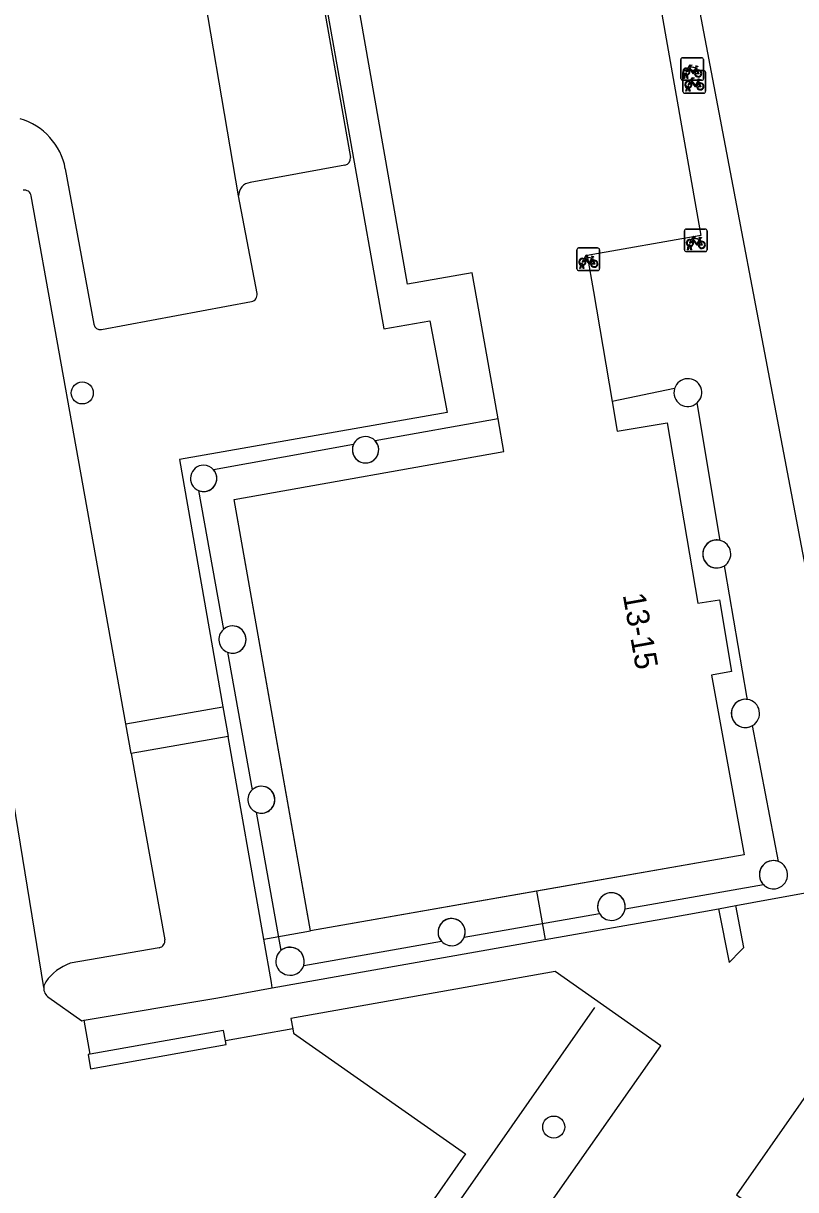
# Model space of a CAD drawing. Extents: x 152881 to 155736, y 382924 to 386919.
# Drawn here: x 155208.5 to 155242.8, y 385255.6 to 385307.3 of the extents above; entities that cross this region are included whole.
import ezdxf

# ---------------------------------------------------------------- set-up
doc = ezdxf.new("R2010")
doc.units = 0
for name, color, linetype in [('IMGEO_Boom', 7, 'Continuous'), ('IMGEO_Fietsenrek', 7, 'Continuous'), ('IMGEO_Hek', 7, 'Continuous'), ('IMGEO_Pand', 7, 'Continuous'), ('IMGEO_Pand_nummerreeks', 7, 'Continuous'), ('IMGEO_Pand_overbouw', 7, 'Continuous'), ('IMGEO_Parkeervlak_open', 7, 'Continuous'), ('IMGEO_Rijbaan_lokaal_open', 7, 'Continuous'), ('IMGEO_Voetpad_halfverhard', 7, 'Continuous'), ('IMGEO_Voetpad_open', 7, 'Continuous')]:
    doc.layers.add(name, color=color, linetype=linetype)

msp = doc.modelspace()

# ---------------------------------------------------------------- linework, layer by layer
at = {"layer": 'IMGEO_Boom'}
for centre in [(155211.143, 385290.912), (155232.043, 385258.375)]:
    msp.add_circle(centre, 0.489, dxfattribs=at)
at = {"layer": 'IMGEO_Fietsenrek'}
for p, q in [((155237.676, 385304.847), (155237.676, 385305.688)), ((155237.676, 385305.688), (155237.676, 385304.847)), ((155237.751, 385305.772), (155238.592, 385305.772)), ((155238.592, 385305.772), (155237.751, 385305.772)), ((155238.676, 385305.697), (155238.676, 385304.856)), ((155238.676, 385304.856), (155238.676, 385305.697)), ((155237.769, 385304.274), (155237.769, 385305.115)), ((155237.769, 385305.115), (155237.769, 385304.274)), ((155237.803, 385304.856), (155237.842, 385305.016)), ((155237.844, 385305.199), (155238.685, 385305.199)), ((155238.685, 385305.199), (155237.844, 385305.199)), ((155237.914, 385305.028), (155237.913, 385305.032)), ((155237.945, 385305.039), (155237.946, 385305.032)), ((155238.363, 385305.321), (155238.399, 385305.226)), ((155238.769, 385305.124), (155238.769, 385304.283)), ((155238.769, 385304.283), (155238.769, 385305.124)), ((155238.601, 385304.772), (155237.76, 385304.772)), ((155237.76, 385304.772), (155238.601, 385304.772)), ((155237.837, 385304.856), (155237.803, 385304.856)), ((155237.872, 385305.004), (155237.837, 385304.856)), ((155237.955, 385304.856), (155237.921, 385304.998)), ((155237.953, 385305.002), (155237.988, 385304.856)), ((155237.988, 385304.856), (155237.955, 385304.856)), ((155238.456, 385304.748), (155238.492, 385304.653)), ((155238.694, 385304.199), (155237.853, 385304.199)), ((155237.853, 385304.199), (155238.694, 385304.199)), ((155237.896, 385304.283), (155237.935, 385304.443)), ((155237.93, 385304.283), (155237.896, 385304.283)), ((155237.965, 385304.431), (155237.93, 385304.283)), ((155238.007, 385304.455), (155238.006, 385304.459)), ((155238.048, 385304.283), (155238.014, 385304.425)), ((155238.038, 385304.466), (155238.039, 385304.459)), ((155238.046, 385304.429), (155238.081, 385304.283)), ((155238.081, 385304.283), (155238.048, 385304.283)), ((155237.835, 385297.251), (155237.835, 385298.092)), ((155237.835, 385298.092), (155237.835, 385297.251)), ((155237.91, 385298.176), (155238.751, 385298.176)), ((155238.751, 385298.176), (155237.91, 385298.176)), ((155238.835, 385298.101), (155238.835, 385297.26)), ((155238.835, 385297.26), (155238.835, 385298.101)), ((155233.069, 385296.413), (155233.069, 385297.254)), ((155233.069, 385297.254), (155233.069, 385296.413)), ((155233.144, 385297.338), (155233.985, 385297.338)), ((155233.985, 385297.338), (155233.144, 385297.338)), ((155234.069, 385297.263), (155234.069, 385296.422)), ((155234.069, 385296.422), (155234.069, 385297.263)), ((155237.962, 385297.26), (155238.001, 385297.42)), ((155237.996, 385297.26), (155237.962, 385297.26)), ((155238.031, 385297.408), (155237.996, 385297.26)), ((155238.073, 385297.432), (155238.072, 385297.436)), ((155238.114, 385297.26), (155238.08, 385297.402)), ((155238.104, 385297.443), (155238.105, 385297.436)), ((155238.112, 385297.406), (155238.147, 385297.26)), ((155238.147, 385297.26), (155238.114, 385297.26)), ((155238.522, 385297.725), (155238.558, 385297.63)), ((155233.756, 385296.887), (155233.792, 385296.792)), ((155238.76, 385297.176), (155237.919, 385297.176)), ((155237.919, 385297.176), (155238.76, 385297.176)), ((155233.994, 385296.338), (155233.153, 385296.338)), ((155233.153, 385296.338), (155233.994, 385296.338)), ((155233.196, 385296.422), (155233.235, 385296.582)), ((155233.23, 385296.422), (155233.196, 385296.422)), ((155233.265, 385296.57), (155233.23, 385296.422)), ((155233.307, 385296.594), (155233.306, 385296.598)), ((155233.348, 385296.422), (155233.314, 385296.564)), ((155233.338, 385296.605), (155233.339, 385296.598)), ((155233.346, 385296.568), (155233.381, 385296.422)), ((155233.381, 385296.422), (155233.348, 385296.422))]:
    msp.add_line(p, q, dxfattribs=at)
for points in [[(155238.01, 385305.246), (155237.958, 385305.156), (155237.918, 385305.131), (155237.919, 385305.178), (155237.974, 385305.272)], [(155237.989, 385305.298), (155238.084, 385305.462), (155238.17, 385305.448), (155238.172, 385305.439), (155238.116, 385305.428), (155238.089, 385305.383), (155238.345, 385305.342)], [(155238.285, 385305.054), (155238.235, 385305.054), (155238.044, 385305.305), (155238.025, 385305.273)], [(155238.332, 385305.317), (155238.075, 385305.358), (155238.058, 385305.329), (155238.225, 385305.109), (155238.332, 385305.317)], [(155238.38, 385305.219), (155238.35, 385305.296), (155238.241, 385305.078), (155238.284, 385305.078)], [(155238.314, 385305.078), (155238.434, 385305.077), (155238.39, 385305.191)], [(155238.41, 385305.198), (155238.465, 385305.053), (155238.315, 385305.053)], [(155238.345, 385305.342), (155238.37, 385305.391), (155238.364, 385305.395), (155238.341, 385305.399), (155238.329, 385305.406), (155238.328, 385305.409), (155238.33, 385305.414), (155238.425, 385305.399), (155238.427, 385305.389), (155238.417, 385305.376), (155238.405, 385305.37), (155238.391, 385305.376), (155238.363, 385305.321)], [(155238.103, 385304.673), (155238.051, 385304.583), (155238.011, 385304.558), (155238.012, 385304.605), (155238.067, 385304.699)], [(155238.082, 385304.725), (155238.177, 385304.889), (155238.263, 385304.875), (155238.265, 385304.866), (155238.209, 385304.855), (155238.182, 385304.81), (155238.438, 385304.769)], [(155238.378, 385304.481), (155238.328, 385304.481), (155238.137, 385304.732), (155238.118, 385304.7)], [(155238.425, 385304.744), (155238.168, 385304.785), (155238.151, 385304.756), (155238.318, 385304.536), (155238.425, 385304.744)], [(155238.473, 385304.646), (155238.443, 385304.723), (155238.334, 385304.505), (155238.377, 385304.505)], [(155238.407, 385304.505), (155238.527, 385304.504), (155238.483, 385304.618)], [(155238.503, 385304.625), (155238.558, 385304.48), (155238.408, 385304.48)], [(155238.438, 385304.769), (155238.463, 385304.818), (155238.457, 385304.822), (155238.434, 385304.826), (155238.422, 385304.833), (155238.421, 385304.836), (155238.423, 385304.841), (155238.518, 385304.826), (155238.52, 385304.816), (155238.51, 385304.803), (155238.498, 385304.797), (155238.484, 385304.803), (155238.456, 385304.748)], [(155238.148, 385297.702), (155238.243, 385297.866), (155238.329, 385297.852), (155238.331, 385297.843), (155238.275, 385297.832), (155238.248, 385297.787), (155238.504, 385297.746)], [(155238.504, 385297.746), (155238.529, 385297.795), (155238.523, 385297.799), (155238.5, 385297.803), (155238.488, 385297.81), (155238.487, 385297.813), (155238.489, 385297.818), (155238.584, 385297.803), (155238.586, 385297.793), (155238.576, 385297.78), (155238.564, 385297.774), (155238.55, 385297.78), (155238.522, 385297.725)], [(155238.169, 385297.65), (155238.117, 385297.56), (155238.077, 385297.535), (155238.078, 385297.582), (155238.133, 385297.676)], [(155238.444, 385297.458), (155238.394, 385297.458), (155238.203, 385297.709), (155238.184, 385297.677)], [(155238.491, 385297.721), (155238.234, 385297.762), (155238.217, 385297.733), (155238.384, 385297.513), (155238.491, 385297.721)], [(155238.539, 385297.623), (155238.509, 385297.7), (155238.4, 385297.482), (155238.443, 385297.482)], [(155238.473, 385297.482), (155238.593, 385297.481), (155238.549, 385297.595)], [(155238.569, 385297.602), (155238.624, 385297.457), (155238.474, 385297.457)], [(155233.403, 385296.812), (155233.351, 385296.722), (155233.311, 385296.697), (155233.312, 385296.744), (155233.367, 385296.838)], [(155233.382, 385296.864), (155233.477, 385297.028), (155233.563, 385297.014), (155233.565, 385297.005), (155233.509, 385296.994), (155233.482, 385296.949), (155233.738, 385296.908)], [(155233.678, 385296.62), (155233.628, 385296.62), (155233.437, 385296.871), (155233.418, 385296.839)], [(155233.725, 385296.883), (155233.468, 385296.924), (155233.451, 385296.895), (155233.618, 385296.675), (155233.725, 385296.883)], [(155233.773, 385296.785), (155233.743, 385296.862), (155233.634, 385296.644), (155233.677, 385296.644)], [(155233.707, 385296.644), (155233.827, 385296.643), (155233.783, 385296.757)], [(155233.803, 385296.764), (155233.858, 385296.619), (155233.708, 385296.619)], [(155233.738, 385296.908), (155233.763, 385296.957), (155233.757, 385296.961), (155233.734, 385296.965), (155233.722, 385296.972), (155233.721, 385296.975), (155233.723, 385296.98), (155233.818, 385296.965), (155233.82, 385296.955), (155233.81, 385296.942), (155233.798, 385296.936), (155233.784, 385296.942), (155233.756, 385296.887)]]:
    msp.add_lwpolyline(points, dxfattribs=at)
for centre, radius, start, end in [((155237.754, 385305.694), 0.0779, 92.4484, 184.2845), ((155237.754, 385305.694), 0.0779, 92.4484, 184.2845), ((155238.598, 385305.694), 0.0779, 2.4484, 94.2845), ((155238.598, 385305.694), 0.0779, 2.4484, 94.2845), ((155237.916, 385305.157), 0.159, 62.6766, 242.1369), ((155237.847, 385305.121), 0.0779, 92.4484, 184.2845), ((155237.847, 385305.121), 0.0779, 92.4484, 184.2845), ((155237.916, 385305.157), 0.129, 63.3192, 238.903), ((155237.896, 385305.028), 0.0499, 12.8025, 158.6934), ((155237.896, 385305.028), 0.0174, 12.8025, 163.4502), ((155237.916, 385305.157), 0.129, 253.415, 269.0204), ((155237.916, 385305.157), 0.129, 283.6043, 43.4302), ((155237.916, 385305.157), 0.159, 283.5766, 46.6042), ((155238.443, 385305.073), 0.159, 113.3408, 178.3217), ((155238.443, 385305.073), 0.159, 187.0065, 105.7708), ((155238.443, 385305.073), 0.129, 113.923, 177.9556), ((155238.443, 385305.073), 0.129, 188.6715, 104.5883), ((155238.691, 385305.121), 0.0779, 2.4484, 94.2845), ((155238.691, 385305.121), 0.0779, 2.4484, 94.2845), ((155237.754, 385304.85), 0.0779, 182.4484, 274.2845), ((155237.754, 385304.85), 0.0779, 182.4484, 274.2845), ((155238.009, 385304.584), 0.159, 62.6766, 242.1369), ((155237.916, 385305.157), 0.159, 253.9967, 271.7867), ((155238.009, 385304.584), 0.129, 63.3192, 238.903), ((155237.989, 385304.455), 0.0499, 12.8025, 158.6934), ((155238.009, 385304.584), 0.129, 283.6043, 43.4302), ((155238.009, 385304.584), 0.159, 283.5766, 46.6042), ((155238.536, 385304.5), 0.159, 113.3408, 178.3217), ((155238.536, 385304.5), 0.159, 187.0065, 105.7708), ((155238.536, 385304.5), 0.129, 113.923, 177.9556), ((155238.536, 385304.5), 0.129, 188.6715, 104.5883), ((155238.598, 385304.85), 0.0779, 272.4484, 4.2845), ((155238.598, 385304.85), 0.0779, 272.4484, 4.2845), ((155237.847, 385304.277), 0.0779, 182.4484, 274.2845), ((155237.847, 385304.277), 0.0779, 182.4484, 274.2845), ((155238.009, 385304.584), 0.159, 253.9967, 271.7867), ((155237.989, 385304.455), 0.0174, 12.8025, 163.4502), ((155238.009, 385304.584), 0.129, 253.415, 269.0204), ((155238.691, 385304.277), 0.0779, 272.4484, 4.2845), ((155238.691, 385304.277), 0.0779, 272.4484, 4.2845), ((155237.913, 385298.098), 0.0779, 92.4484, 184.2845), ((155237.913, 385298.098), 0.0779, 92.4484, 184.2845), ((155238.757, 385298.098), 0.0779, 2.4484, 94.2845), ((155238.757, 385298.098), 0.0779, 2.4484, 94.2845), ((155233.147, 385297.26), 0.0779, 92.4484, 184.2845), ((155233.147, 385297.26), 0.0779, 92.4484, 184.2845), ((155233.991, 385297.26), 0.0779, 2.4484, 94.2845), ((155233.991, 385297.26), 0.0779, 2.4484, 94.2845), ((155238.075, 385297.561), 0.159, 62.6766, 242.1369), ((155238.075, 385297.561), 0.129, 63.3192, 238.903), ((155238.055, 385297.432), 0.0499, 12.8025, 158.6934), ((155238.075, 385297.561), 0.159, 253.9967, 271.7867), ((155238.055, 385297.432), 0.0174, 12.8025, 163.4502), ((155238.075, 385297.561), 0.129, 253.415, 269.0204), ((155238.075, 385297.561), 0.129, 283.6043, 43.4302), ((155238.075, 385297.561), 0.159, 283.5766, 46.6042), ((155238.602, 385297.477), 0.159, 113.3408, 178.3217), ((155238.602, 385297.477), 0.159, 187.0065, 105.7708), ((155238.602, 385297.477), 0.129, 113.923, 177.9556), ((155238.602, 385297.477), 0.129, 188.6715, 104.5883), ((155238.757, 385297.254), 0.0779, 272.4484, 4.2845), ((155238.757, 385297.254), 0.0779, 272.4484, 4.2845), ((155233.309, 385296.723), 0.159, 62.6766, 242.1369), ((155233.309, 385296.723), 0.129, 63.3192, 238.903), ((155233.309, 385296.723), 0.129, 283.6043, 43.4302), ((155233.309, 385296.723), 0.159, 283.5766, 46.6042), ((155233.836, 385296.639), 0.159, 113.3408, 178.3217), ((155233.836, 385296.639), 0.159, 187.0065, 105.7708), ((155233.836, 385296.639), 0.129, 113.923, 177.9556), ((155233.836, 385296.639), 0.129, 188.6715, 104.5883), ((155237.913, 385297.254), 0.0779, 182.4484, 274.2845), ((155237.913, 385297.254), 0.0779, 182.4484, 274.2845), ((155233.147, 385296.416), 0.0779, 182.4484, 274.2845), ((155233.147, 385296.416), 0.0779, 182.4484, 274.2845), ((155233.289, 385296.594), 0.0499, 12.8025, 158.6934), ((155233.309, 385296.723), 0.159, 253.9967, 271.7867), ((155233.289, 385296.594), 0.0174, 12.8025, 163.4502), ((155233.309, 385296.723), 0.129, 253.415, 269.0204), ((155233.991, 385296.416), 0.0779, 272.4484, 4.2845), ((155233.991, 385296.416), 0.0779, 272.4484, 4.2845)]:
    msp.add_arc(centre, radius, start, end, dxfattribs=at)
at = {"layer": 'IMGEO_Hek'}
msp.add_lwpolyline([(155222.768, 385247.792), (155233.861, 385263.666)], dxfattribs=at)
at = {"layer": 'IMGEO_Pand'}
for points in [[(155221.26, 385267.071), (155220.388, 385271.995), (155217.872, 385286.193), (155229.836, 385288.313), (155229.578, 385289.769), (155228.738, 385294.514), (155228.432, 385296.24), (155225.556, 385295.735), (155218.64, 385335.1)], [(155236.615, 385308.968), (155238.561, 385297.888), (155233.524, 385297.002), (155233.796, 385295.402), (155234.623, 385290.536), (155234.847, 385289.218), (155237.065, 385289.595), (155238.427, 385281.592), (155239.38, 385281.749), (155239.913, 385278.573), (155239.026, 385278.41), (155240.487, 385270.437), (155231.28, 385268.825)], [(155231.28, 385268.825), (155221.26, 385267.071)]]:
    msp.add_lwpolyline(points, dxfattribs=at)
for centre, radius, start, end in [((155237.981, 385290.925), 0.614, 162.4131, 312.5112), ((155237.985, 385290.93), 0.616, 311.9155, 163.0087), ((155223.7, 385288.394), 0.584, 157.1979, 269.921), ((155223.698, 385288.396), 0.582, 89.8707, 157.2634), ((155223.7, 385288.397), 0.581, 42.9862, 90.0658), ((155223.699, 385288.394), 0.584, 269.9744, 43.1649), ((155216.525, 385287.127), 0.584, 90.0587, 246.9681), ((155216.526, 385287.132), 0.579, 40.906, 90.2061), ((155216.525, 385287.127), 0.584, 269.9307, 41.1814), ((155216.529, 385287.154), 0.611, 247.6128, 269.5741), ((155239.267, 385283.775), 0.621, 92.3835, 276.0178), ((155239.265, 385283.797), 0.6, 75.3484, 92.3286), ((155239.267, 385283.775), 0.62, 302.8989, 76.0092), ((155239.26, 385283.789), 0.636, 276.4987, 302.7555), ((155217.802, 385279.982), 0.603, 132.0143, 248.1445), ((155217.801, 385279.985), 0.6, 89.9386, 132.1364), ((155217.802, 385279.982), 0.603, 269.9525, 90.0475), ((155217.804, 385279.994), 0.614, 248.4247, 269.8422), ((155240.538, 385276.707), 0.627, 102.8722, 254.4875), ((155240.535, 385276.715), 0.618, 81.1536, 102.7963), ((155240.537, 385276.707), 0.626, 300.0861, 81.4871), ((155240.536, 385276.706), 0.626, 254.6502, 300.2737), ((155219.079, 385272.887), 0.592, 89.8135, 133.5482), ((155219.082, 385272.883), 0.597, 269.952, 90.048), ((155219.082, 385272.883), 0.597, 133.4863, 246.7226), ((155219.08, 385272.879), 0.593, 246.784, 270.1276), ((155241.779, 385269.559), 0.625, 97.1764, 224.3353), ((155241.781, 385269.562), 0.622, 69.2973, 97.3938), ((155241.779, 385269.559), 0.625, 277.9472, 69.1635), ((155241.777, 385269.555), 0.621, 224.183, 278.1106), ((155234.595, 385268.149), 0.613, 80.4911, 209.8045), ((155234.596, 385268.148), 0.613, 350.1144, 80.6244), ((155234.596, 385268.15), 0.615, 209.8212, 270.9844), ((155234.595, 385268.149), 0.614, 271.1235, 350.0473), ((155227.516, 385267.015), 0.602, 87.9786, 221.9001), ((155227.515, 385267.014), 0.602, 338.2752, 87.9433), ((155227.516, 385267.015), 0.602, 221.8665, 338.1819), ((155220.344, 385265.728), 0.615, 73.2631, 130.4641), ((155220.369, 385265.719), 0.617, 343.0855, 75.7837), ((155220.346, 385265.724), 0.62, 130.3764, 258.8912), ((155220.367, 385265.72), 0.62, 256.9396, 343.0372)]:
    msp.add_arc(centre, radius, start, end, dxfattribs=at)
at = {"layer": 'IMGEO_Pand_overbouw'}
for points in [[(155237.396, 385291.11), (155234.623, 385290.536), (155234.847, 385289.218), (155237.065, 385289.595), (155238.427, 385281.592), (155239.38, 385281.749), (155239.913, 385278.573), (155239.026, 385278.41), (155240.487, 385270.437), (155221.26, 385267.071), (155217.872, 385286.193), (155229.836, 385288.313), (155229.578, 385289.769), (155224.125, 385288.793)], [(155239.417, 385284.377), (155238.396, 385290.472)], [(155223.161, 385288.621), (155216.964, 385287.511)], [(155216.296, 385286.589), (155217.399, 385280.43)], [(155239.633, 385283.084), (155239.604, 385283.254)], [(155240.63, 385277.326), (155240.601, 385277.479), (155239.633, 385283.084)], [(155217.578, 385279.423), (155218.671, 385273.316)], [(155242.001, 385270.144), (155240.851, 385276.166)], [(155218.846, 385272.334), (155219.945, 385266.196)], [(155235.2, 385268.043), (155241.332, 385269.122)], [(155228.075, 385266.791), (155234.063, 385267.844)], [(155220.96, 385265.539), (155227.068, 385266.613)]]:
    msp.add_lwpolyline(points, dxfattribs=at)
for centre, radius, start, end in [((155237.981, 385290.925), 0.614, 162.4131, 312.5112), ((155223.699, 385288.394), 0.584, 157.1062, 43.1267), ((155216.524, 385287.127), 0.584, 246.9952, 41.1572), ((155239.266, 385283.775), 0.621, 75.9382, 302.9699), ((155217.802, 385279.982), 0.603, 248.1403, 132.0184), ((155240.537, 385276.707), 0.626, 81.4241, 300.1491), ((155219.081, 385272.883), 0.597, 246.7908, 133.4182), ((155241.78, 385269.559), 0.626, 69.2738, 224.3088), ((155234.596, 385268.148), 0.613, 350.149, 209.7059), ((155227.516, 385267.015), 0.602, 338.1941, 221.8543), ((155220.348, 385265.707), 0.634, 344.6564, 129.5144)]:
    msp.add_arc(centre, radius, start, end, dxfattribs=at)
at = {"layer": 'IMGEO_Parkeervlak_open'}
for points in [[(155217.142, 385337.508), (155217.044, 385337.456), (155216.999, 385337.43), (155216.957, 385337.399), (155216.918, 385337.366), (155216.882, 385337.329), (155216.849, 385337.288), (155216.821, 385337.245), (155216.796, 385337.2), (155216.775, 385337.152), (155216.759, 385337.103), (155216.747, 385337.053), (155216.74, 385337.002), (155216.738, 385336.95), (155216.74, 385336.898), (155216.747, 385336.847), (155217.107, 385334.819), (155217.164, 385334.497), (155223.027, 385301.353)], [(155222.785, 385301.006), (155218.592, 385300.24)], [(155213.084, 385276.243), (155208.887, 385299.655)], [(155213.32, 385274.929), (155214.8, 385266.672)], [(155214.556, 385266.324), (155210.614, 385265.632)]]:
    msp.add_lwpolyline(points, dxfattribs=at)
for centre, radius, start, end in [((155222.732, 385301.301), 0.3, 280.2208, 9.9949), ((155208.591, 385299.601), 0.301, 10.3787, 100.9771), ((155218.66, 385299.656), 0.588, 96.6003, 180.8089), ((155214.505, 385266.62), 0.3, 279.8682, 10.0595), ((155211.352, 385263.529), 2.229, 109.3432, 144.6677), ((155209.928, 385264.529), 0.489, 143.7199, 176.6668)]:
    msp.add_arc(centre, radius, start, end, dxfattribs=at)
at = {"layer": 'IMGEO_Rijbaan_lokaal_open'}
for points in [[(155218.072, 385299.648), (155212.177, 385334.324), (155211.966, 385335.54)], [(155210.394, 385300.851), (155211.654, 385293.961)], [(155209.44, 385264.557), (155203.748, 385299.407)], [(155218.891, 385295.314), (155218.072, 385299.648)], [(155212.005, 385293.72), (155218.651, 385294.963)], [(155209.663, 385264.121), (155211.131, 385263.089), (155211.226, 385263.105)], [(155211.496, 385261.601), (155211.226, 385263.105)], [(155220.471, 385262.731), (155217.499, 385262.189)], [(155220.471, 385262.731), (155220.509, 385262.535), (155228.135, 385257.182), (155221.787, 385248.092)], [(155211.496, 385261.601), (155211.403, 385261.584), (155211.517, 385260.96), (155217.529, 385262.035), (155217.499, 385262.189)]]:
    msp.add_lwpolyline(points, dxfattribs=at)
for centre, radius, start, end in [((155207.605, 385300.339), 2.836, 10.4022, 73.8038), ((155218.596, 385295.258), 0.3, 280.5745, 10.6999), ((155211.951, 385294.017), 0.302, 190.7072, 280.3451), ((155209.928, 385264.532), 0.489, 177.0107, 237.1658)]:
    msp.add_arc(centre, radius, start, end, dxfattribs=at)
at = {"layer": 'IMGEO_Voetpad_halfverhard'}
msp.add_lwpolyline([(155219.565, 385264.547), (155219.525, 385264.776), (155219.186, 385266.708)], dxfattribs=at)
at = {"layer": 'IMGEO_Voetpad_open'}
for points in [[(155232.782, 385339.093), (155231.347, 385338.838), (155216.948, 385336.279), (155217.203, 385334.845), (155224.504, 385293.751), (155226.555, 385294.115), (155227.312, 385290.042), (155215.457, 385287.964), (155217.381, 385276.997)], [(155240.113, 385268.192), (155240.833, 385268.324), (155242.699, 385268.667), (155245.841, 385269.229), (155245.667, 385270.214), (155235.608, 385323.188), (155233.038, 385337.653), (155232.782, 385339.093)], [(155213.084, 385276.243), (155217.381, 385276.997)], [(155217.381, 385276.997), (155217.612, 385275.682)], [(155213.32, 385274.929), (155213.084, 385276.243)], [(155217.612, 385275.682), (155213.32, 385274.929)], [(155219.186, 385266.708), (155217.612, 385275.682)], [(155254.396, 385275.757), (155240.133, 385255.369), (155243.121, 385253.259)], [(155231.28, 385268.825), (155231.659, 385266.68)], [(155231.659, 385266.68), (155237.123, 385267.643), (155239.342, 385268.05)], [(155239.342, 385268.05), (155240.113, 385268.192)], [(155239.342, 385268.05), (155239.821, 385265.667), (155240.338, 385266.196), (155240.47, 385266.334), (155240.113, 385268.192)], [(155219.186, 385266.708), (155221.26, 385267.071)], [(155219.565, 385264.547), (155231.659, 385266.68)], [(155222.038, 385247.916), (155224.49, 385246.199), (155229.952, 385253.964), (155230.765, 385253.39), (155236.787, 385261.972), (155232.097, 385265.263), (155220.383, 385263.186), (155220.471, 385262.731)], [(155211.226, 385263.105), (155217.151, 385264.107), (155219.565, 385264.547)], [(155217.499, 385262.189), (155217.406, 385262.659), (155211.496, 385261.601)]]:
    msp.add_lwpolyline(points, dxfattribs=at)

# ---------------------------------------------------------------- texts
at = {"layer": 'IMGEO_Pand_nummerreeks'}
msp.add_text('13-15', height=1, rotation=280.1297, dxfattribs=at).set_placement((155235.096, 385281.962))

doc.saveas('drawing.dxf')
